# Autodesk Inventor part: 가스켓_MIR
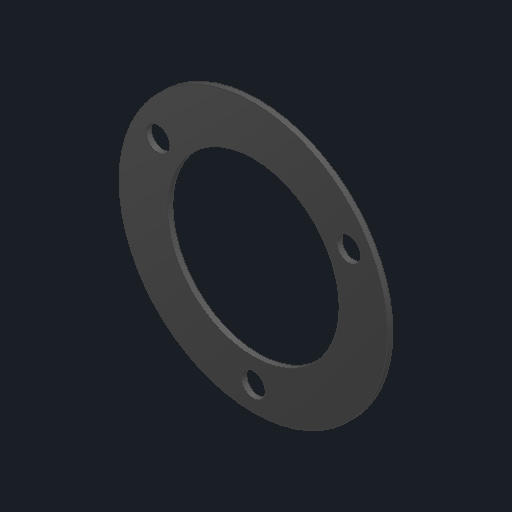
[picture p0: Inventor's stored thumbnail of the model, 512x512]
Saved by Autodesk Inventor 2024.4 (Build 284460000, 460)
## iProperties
Created: 2025-10
Part Number: 가스켓_MIR
Material: 스테인리스스틸
Document SubType Name: Modeling
Designer: user
Density: 8 g/cm^3
Appearance: 기본값
Author: jhkim
Sending System: Autodesk Inventor 2026
Preprocessor: ST-DEVELOPER v20.1
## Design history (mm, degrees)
derived "가스켓.ipt"
feature "솔리드2::가스켓.ipt" dims "d0" = 10
tag "피쳐 태그1"
node "솔리드2"
